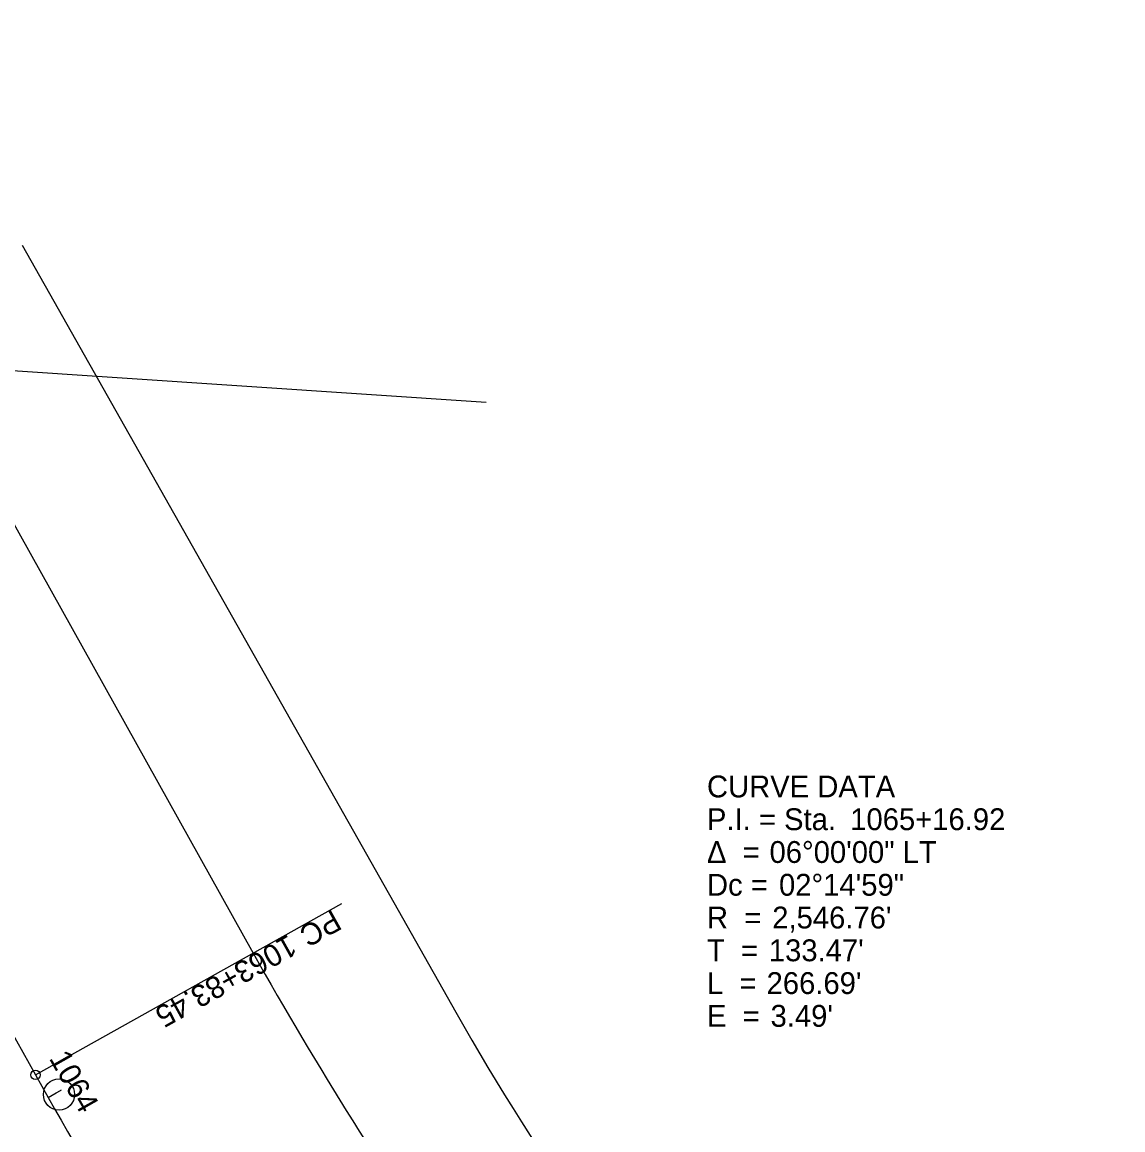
# Model space of a CAD drawing. Extents: x 1947854 to 1951648, y 150068 to 154534.
# Drawn here: x 1948658 to 1949363, y 152335 to 153045 of the extents above; entities that cross this region are included whole.
import ezdxf

# ---------------------------------------------------------------- set-up
doc = ezdxf.new("R2010")
doc.units = 0
for name, color, linetype in [('DR_X_Cells', 7, 'Continuous'), ('DR_X_Elev_Flow', 7, 'Continuous'), ('DV_X_Section_VMS_Line', 7, 'Continuous'), ('GE_X_Alignment', 7, 'Continuous'), ('GE_X_Alignment_100_Curve_Data', 7, 'Continuous'), ('RW_X_Esmt_LA', 7, 'Continuous'), ('SC_Scratch1', 7, 'Continuous'), ('SN_X_Public', 7, 'Continuous'), ('SV_P_Control_Cells_Set', 7, 'Continuous'), ('SV_X_Random_Point', 7, 'Continuous')]:
    doc.layers.add(name, color=color, linetype=linetype)

msp = doc.modelspace()

# ---------------------------------------------------------------- linework, layer by layer
at = {"layer": 'DR_X_Elev_Flow'}
msp.add_line((1948666.27, 152370.56), (1948862.67, 152480.34), dxfattribs=at)
msp.add_circle((1948666.27, 152370.56), 3, dxfattribs=at)
at = {"layer": 'DV_X_Section_VMS_Line'}
msp.add_line((1947854.28, 152874.81), (1948955.39, 152801.74), dxfattribs=at)
at = {"layer": 'GE_X_Alignment'}
msp.add_line((1948127.85, 153333.82), (1948666.27, 152370.56), dxfattribs=at)
msp.add_arc((1950889.32, 153613.15), 2546.76, 209.20338, 215.20324, dxfattribs=at)
at = {"layer": 'RW_X_Esmt_LA'}
msp.add_line((1948472.47, 153045.2), (1948805.93, 152448.62), dxfattribs=at)
msp.add_arc((1950889.32, 153613.15), 2386.76, 209.20338, 215.20324, dxfattribs=at)
at = {"layer": 'SC_Scratch1'}
msp.add_line((1948657.8, 152902.37), (1948935.83, 152410.68), dxfattribs=at)
msp.add_circle((1948681.43, 152358.05), 10, dxfattribs=at)
msp.add_arc((1950328.58, 153198.22), 1600, 209.48645, 232.90075, dxfattribs=at)
at = {"layer": 'SN_X_Public'}
for p, q in [((1948666.27, 152370.56), (1948862.67, 152480.34)), ((1948674.39, 152356.14), (1948683.09, 152361.07))]:
    msp.add_line(p, q, dxfattribs=at)
msp.add_circle((1948666.27, 152370.56), 3, dxfattribs=at)
at = {"layer": 'SV_X_Random_Point'}
for p, q in [((1948666.27, 152370.56), (1948862.67, 152480.34)), ((1948674.39, 152356.14), (1948679.61, 152359.1))]:
    msp.add_line(p, q, dxfattribs=at)
msp.add_circle((1948666.27, 152370.56), 3, dxfattribs=at)

# ---------------------------------------------------------------- texts
at = {"layer": 'DR_X_Cells'}
for s, p in [('CURVE DATA', (1949096.84, 152548.41)), ('P.I. = Sta. ', (1949096.84, 152527.41)), ('1065+16.92', (1949188.68, 152527.41)), ('Δ  = ', (1949096.84, 152506.41)), ('06°00\'00" LT', (1949136.95, 152506.41)), ('Dc = ', (1949096.84, 152485.41)), ('02°14\'59"', (1949143.03, 152485.41)), ('R  = ', (1949096.84, 152464.41)), ("2,546.76'", (1949138.68, 152464.41)), ('T  = ', (1949096.84, 152443.41)), ("133.47'", (1949136.5, 152443.41)), ('L  = ', (1949096.84, 152422.41)), ("266.69'", (1949135.07, 152422.41)), ('E  = ', (1949096.84, 152401.41)), ("3.49'", (1949137.6, 152401.41))]:
    msp.add_text(s, height=14, dxfattribs=at).set_placement(p)
at = {"layer": 'DR_X_Elev_Flow'}
for s, p in [('PC', (1948857.01, 152476.9)), ('1063+83.45', (1948828.55, 152460.99))]:
    msp.add_text(s, height=14, rotation=209.20338, dxfattribs=at).set_placement(p)
at = {"layer": 'GE_X_Alignment_100_Curve_Data'}
for s, p in [('CURVE DATA', (1949096.84, 152548.41)), ('P.I. = Sta. ', (1949096.84, 152527.41)), ('1065+16.92', (1949188.68, 152527.41)), ('Δ  = ', (1949096.84, 152506.41)), ('06°00\'00" LT', (1949136.95, 152506.41)), ('Dc = ', (1949096.84, 152485.41)), ('02°14\'59"', (1949143.03, 152485.41)), ('R  = ', (1949096.84, 152464.41)), ("2,546.76'", (1949138.68, 152464.41)), ('T  = ', (1949096.84, 152443.41)), ("133.47'", (1949136.5, 152443.41)), ('L  = ', (1949096.84, 152422.41)), ("266.69'", (1949135.07, 152422.41)), ('E  = ', (1949096.84, 152401.41)), ("3.49'", (1949137.6, 152401.41))]:
    msp.add_text(s, height=14, dxfattribs=at).set_placement(p)
at = {"layer": 'SN_X_Public'}
for s, rotation, p in [('PC', 209.20338, (1948857.01, 152476.9)), ('1063+83.45', 209.20338, (1948828.55, 152460.99)), ('1064', 299.57571, (1948674.79, 152381.23))]:
    msp.add_text(s, height=14, rotation=rotation, dxfattribs=at).set_placement(p)
at = {"layer": 'SV_P_Control_Cells_Set'}
for s, p in [('CURVE DATA', (1949096.84, 152548.41)), ('P.I. = Sta. ', (1949096.84, 152527.41)), ('1065+16.92', (1949188.68, 152527.41)), ('Δ  = ', (1949096.84, 152506.41)), ('06°00\'00" LT', (1949136.95, 152506.41)), ('Dc = ', (1949096.84, 152485.41)), ('02°14\'59"', (1949143.03, 152485.41)), ('R  = ', (1949096.84, 152464.41)), ("2,546.76'", (1949138.68, 152464.41)), ('T  = ', (1949096.84, 152443.41)), ("133.47'", (1949136.5, 152443.41)), ('L  = ', (1949096.84, 152422.41)), ("266.69'", (1949135.07, 152422.41)), ('E  = ', (1949096.84, 152401.41)), ("3.49'", (1949137.6, 152401.41))]:
    msp.add_text(s, height=14, dxfattribs=at).set_placement(p)
at = {"layer": 'SV_X_Random_Point'}
for s, p in [('PC', (1948857.01, 152476.9)), ('1063+83.45', (1948828.55, 152460.99))]:
    msp.add_text(s, height=14, rotation=209.20338, dxfattribs=at).set_placement(p)

doc.saveas('drawing.dxf')
